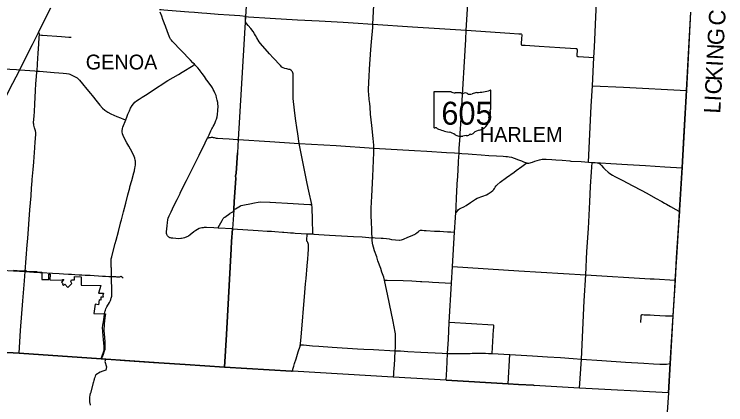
# Model space of a CAD drawing. Extents: x 1729596 to 1925846, y 659247 to 911751.
# Drawn here: x 1855559 to 1898765, y 773722 to 797404 of the extents above; entities that cross this region are included whole.
import ezdxf

# ---------------------------------------------------------------- set-up
doc = ezdxf.new("R2010")
doc.units = 0
for name, color, linetype in [('GM_X_Adjacent_County', 7, 'Continuous'), ('GM_X_Adjacent_County_Text', 7, 'Continuous'), ('GM_X_City_Street', 7, 'Continuous'), ('GM_X_Corporation', 7, 'Continuous'), ('GM_X_County', 7, 'Continuous'), ('GM_X_County_Road', 7, 'Continuous'), ('GM_X_State_Route', 7, 'Continuous'), ('GM_X_State_Shield', 7, 'Continuous'), ('GM_X_Township', 7, 'Continuous'), ('GM_X_Township_Road', 7, 'Continuous'), ('GM_X_Township_Text', 7, 'Continuous')]:
    doc.layers.add(name, color=color, linetype=linetype)

msp = doc.modelspace()

# ---------------------------------------------------------------- linework, layer by layer
at = {"layer": 'GM_X_Adjacent_County'}
msp.add_line((1895282, 774451), (1894201, 757542), dxfattribs=at)
at = {"layer": 'GM_X_City_Street'}
for points in [[(1852214, 782040), (1852297, 782035), (1852381, 782031), (1852490, 782023), (1853564, 781958), (1854813, 781882), (1856233, 781796), (1856759, 781767), (1857122, 781742)], [(1855849, 776844), (1855938, 778232), (1856080, 780022), (1856177, 781246), (1856233, 781796)], [(1860837, 776510), (1860876, 776625), (1861011, 777030), (1861019, 777105), (1861019, 777267), (1861005, 777431), (1860979, 777707), (1860959, 777869), (1860929, 778184), (1860926, 778385), (1860938, 778550), (1860970, 778758), (1861038, 779200), (1861042, 779227)], [(1851242, 777113), (1853977, 776957), (1854746, 776908), (1855849, 776844), (1860837, 776510)], [(1860837, 776510), (1861150, 776489)]]:
    msp.add_lwpolyline(points, dxfattribs=at)
at = {"layer": 'GM_X_Corporation'}
msp.add_lwpolyline([(1855515, 781881), (1855693, 781873), (1855739, 781870), (1855967, 781851), (1856168, 781841), (1856195, 781864), (1856211, 781863), (1856236, 781862), (1856261, 781860), (1856276, 781859), (1856299, 781833), (1856937, 781794), (1856936, 781779), (1857238, 781762), (1857236, 781737), (1857239, 781327), (1857650, 781308), (1857667, 781631), (1857667, 781633), (1857666, 781635), (1857665, 781638), (1857665, 781639), (1857663, 781642), (1857661, 781645), (1857661, 781645), (1857660, 781645), (1857658, 781647), (1857657, 781648), (1857656, 781648), (1857654, 781649), (1857652, 781650), (1857650, 781650), (1857750, 781644), (1857748, 781644), (1857746, 781643), (1857744, 781643), (1857743, 781642), (1857742, 781642), (1857739, 781640), (1857739, 781640), (1857739, 781639), (1857736, 781637), (1857734, 781634), (1857734, 781633), (1857732, 781631), (1857732, 781629), (1857731, 781626), (1857715, 781305), (1858491, 781268), (1858493, 781318), (1858578, 781314), (1858423, 781151), (1858532, 781048), (1858498, 781011), (1858552, 780960), (1858623, 781028), (1858823, 780839), (1859051, 781080), (1858990, 781189), (1859040, 781304), (1859215, 781299), (1859220, 781493), (1859628, 781482), (1859614, 780982), (1860814, 780950), (1860682, 780484), (1860982, 780480), (1860944, 780361), (1860968, 780237), (1860818, 780240), (1860815, 780064), (1860716, 780079), (1860671, 779783), (1860473, 779812), (1860389, 779255), (1861099, 779232), (1861059, 778991), (1861017, 778619), (1861001, 778196), (1861035, 777824), (1861063, 777515), (1861063, 777076), (1861027, 776964), (1860963, 776772), (1860875, 776576), (1860907, 776515), (1861104, 776501), (1861102, 776461), (1861067, 776346), (1861166, 776024), (1861129, 775818), (1860932, 775766), (1860782, 775695), (1860506, 775536), (1860490, 775500), (1860473, 775450), (1860446, 775373), (1860418, 775284), (1860408, 775252), (1860389, 775184), (1860366, 775102), (1860350, 775045), (1860186, 774433), (1860177, 774398), (1860167, 774360), (1860158, 774319), (1860150, 774274), (1860139, 774199), (1860132, 774101), (1860131, 774023), (1860133, 773962), (1860139, 773897), (1860151, 773806), (1860162, 773755), (1860176, 773694)], dxfattribs=at)
at = {"layer": 'GM_X_County'}
msp.add_lwpolyline([(1896629, 797539), (1896376, 792790), (1896278, 791042), (1896113, 788102), (1895956, 785523), (1895947, 785445), (1895896, 784633), (1895772, 782650), (1895741, 782103), (1895686, 781278), (1895557, 779101), (1895391, 776219), (1895282, 774451), (1889887, 774731), (1887135, 774898), (1887084, 774902), (1886187, 774949), (1885545, 774992), (1881788, 775208), (1878568, 775400), (1872453, 775754), (1872401, 775756), (1868321, 776001), (1865938, 776163), (1864331, 776270), (1860837, 776510), (1855849, 776844), (1854746, 776908)], dxfattribs=at)
at = {"layer": 'GM_X_County_Road'}
for points in [[(1877332, 796811), (1877420, 798367), (1877499, 799608), (1877454, 800633), (1877398, 802125), (1877369, 802994)], [(1857028, 796294), (1857277, 796797), (1857775, 797801)], [(1869596, 797271), (1869264, 797299), (1868606, 797350), (1867949, 797398), (1867262, 797449), (1866957, 797476), (1866512, 797510), (1866160, 797537), (1865389, 797594), (1864651, 797652), (1864490, 797665), (1864412, 797670), (1864397, 797669), (1864380, 797664)], [(1864668, 796879), (1864590, 797083), (1864513, 797287), (1864422, 797530)], [(1872512, 792112), (1872490, 792299), (1872490, 792441), (1872490, 792557), (1872490, 792879), (1872488, 793281), (1872492, 793732), (1872489, 793791), (1872473, 793859), (1872454, 793904), (1872424, 793943), (1872389, 793984), (1872352, 794016), (1872303, 794045), (1872239, 794060), (1872103, 794090), (1871997, 794120), (1871888, 794161), (1871806, 794204), (1871722, 794290), (1871282, 794757), (1871051, 795010), (1870503, 795638), (1870435, 795737), (1870300, 795980), (1870212, 796114), (1870156, 796211), (1870067, 796366), (1869918, 796549), (1869770, 796721), (1869677, 796824), (1869643, 796870), (1869617, 796918), (1869609, 796940), (1869604, 796966), (1869603, 796991), (1869604, 797040), (1869606, 797200), (1869596, 797271)], [(1869596, 797271), (1869794, 797255), (1871103, 797168), (1872753, 797073), (1874071, 797014), (1875527, 796924), (1876143, 796885), (1877332, 796811)], [(1896288, 791046), (1896384, 792784), (1896550, 795738), (1896641, 797536)], [(1866503, 794368), (1866405, 794466), (1866272, 794620), (1866088, 794799), (1865870, 795027), (1865711, 795195), (1865579, 795328), (1865290, 795631), (1865178, 795747), (1865101, 795824), (1865042, 795902), (1865004, 795980), (1864969, 796070), (1864868, 796347), (1864745, 796675), (1864687, 796830), (1864668, 796879)], [(1877401, 789284), (1877390, 789464), (1877348, 789877), (1877267, 790662), (1877198, 791335), (1877163, 791768), (1877144, 791994), (1877118, 792235), (1877082, 792567), (1877064, 792727), (1877062, 792815), (1877091, 793291), (1877116, 793631), (1877141, 794076), (1877219, 795256), (1877251, 795728), (1877331, 796597), (1877332, 796811)], [(1877332, 796811), (1879735, 796644), (1881379, 796538), (1883003, 796429), (1885646, 796260), (1886199, 796226), (1886342, 796212), (1886365, 796195), (1886376, 796165), (1886375, 796124), (1886362, 795947), (1886335, 795601), (1886339, 795571), (1886347, 795554), (1886359, 795544), (1886386, 795534), (1886593, 795523), (1887442, 795472), (1888679, 795387), (1889657, 795329), (1889685, 795326), (1889702, 795320), (1889718, 795310), (1889731, 795291), (1889734, 795271), (1889715, 794891), (1889718, 794875), (1889726, 794861), (1889758, 794850), (1889831, 794843), (1890758, 794790)], [(1851209, 784694), (1851326, 784936), (1852148, 786590), (1852443, 787187), (1853141, 788601), (1853675, 789667), (1853798, 789914), (1853979, 790280), (1854272, 790859), (1854392, 791103), (1854649, 791581), (1855260, 792799), (1855898, 794041), (1856273, 794777), (1856673, 795566), (1856869, 795971), (1857028, 796294)], [(1856946, 793960), (1856946, 793960), (1856971, 794394), (1857013, 795045), (1857051, 795598), (1857080, 796004), (1857092, 796153), (1857094, 796187), (1857090, 796216), (1857080, 796243), (1857067, 796263), (1857051, 796280), (1857028, 796294)], [(1862331, 790993), (1862331, 790993), (1862425, 791233), (1862464, 791347), (1862553, 791556), (1862621, 791712), (1862718, 791870), (1862878, 792073), (1862988, 792163), (1863137, 792257), (1863326, 792369), (1863622, 792566), (1863901, 792746), (1864887, 793380), (1865528, 793748), (1865763, 793892), (1866421, 794305), (1866453, 794326), (1866503, 794368)], [(1867241, 793436), (1867175, 793524), (1867110, 793619), (1866968, 793805), (1866845, 793974), (1866805, 794027), (1866710, 794146), (1866624, 794245), (1866569, 794300), (1866503, 794368)], [(1856233, 781796), (1856351, 783427), (1856379, 783803), (1856513, 785538), (1856582, 786399), (1856616, 786866), (1856649, 787292), (1856657, 787391), (1856707, 787988), (1856742, 788435), (1856768, 788759), (1856787, 788996), (1856839, 789647), (1856877, 790103), (1856879, 790157), (1856870, 790238), (1856843, 790340), (1856828, 790389), (1856789, 790519), (1856749, 790673), (1856741, 790738), (1856737, 790808), (1856738, 790844), (1856763, 791215), (1856781, 791498), (1856809, 791946), (1856855, 792786), (1856879, 793181), (1856895, 793405), (1856933, 793880), (1856936, 793913), (1856946, 793960)], [(1867153, 789604), (1867200, 789700), (1867319, 789935), (1867396, 790101), (1867504, 790327), (1867565, 790450), (1867596, 790512), (1867641, 790592), (1867690, 790690), (1867763, 790847), (1867804, 790955), (1867838, 791037), (1867877, 791180), (1867910, 791333), (1867929, 791569), (1867933, 791826), (1867927, 791967), (1867917, 792047), (1867886, 792196), (1867849, 792363), (1867813, 792478), (1867788, 792552), (1867745, 792648), (1867704, 792736), (1867647, 792848), (1867599, 792941), (1867524, 793055), (1867442, 793157), (1867330, 793312), (1867263, 793407), (1867241, 793436)], [(1872927, 777320), (1872945, 777432), (1872978, 777819), (1873212, 780520), (1873251, 781046), (1873282, 781384), (1873344, 782141), (1873381, 782566), (1873402, 782850), (1873426, 783163), (1873427, 783321), (1873418, 783441), (1873405, 783505), (1873393, 783554), (1873368, 783600), (1873335, 783652), (1873325, 783665), (1873319, 783693), (1873320, 783725), (1873324, 783797), (1873340, 783963), (1873351, 784093), (1873606, 784082), (1873683, 784083), (1873682, 784168), (1873669, 784889), (1873663, 785162), (1873657, 785466), (1873655, 785664), (1873627, 785869), (1873446, 786682), (1873351, 787142), (1872964, 789059), (1872863, 789571), (1872778, 790159), (1872727, 790526), (1872666, 790930), (1872604, 791411), (1872559, 791766), (1872513, 792107), (1872512, 792112)], [(1862860, 787938), (1862891, 788070), (1862911, 788154), (1862924, 788278), (1862924, 788410), (1862919, 788484), (1862909, 788555), (1862881, 788678), (1862846, 788780), (1862782, 788915), (1862621, 789214), (1862525, 789400), (1862401, 789615), (1862280, 789828), (1862168, 790041), (1862129, 790158), (1862118, 790274), (1862114, 790336), (1862129, 790467), (1862155, 790566), (1862331, 790993)], [(1895958, 785443), (1895961, 785520), (1896121, 788099), (1896226, 789994), (1896288, 791046)], [(1865634, 786531), (1865642, 786548), (1865861, 787020), (1866012, 787331), (1866508, 788298), (1866790, 788861), (1866977, 789237), (1867126, 789549), (1867153, 789604)], [(1872863, 789571), (1875101, 789435), (1877401, 789284), (1879855, 789132), (1880616, 789098), (1881806, 789028), (1882295, 788997), (1882567, 788975)], [(1878568, 775400), (1878590, 775455), (1878599, 775524), (1878604, 775641), (1878633, 775979), (1878640, 776088), (1878691, 776999), (1878702, 777191), (1878720, 777542), (1878720, 777749), (1878716, 777928), (1878712, 778020), (1878692, 778117), (1878562, 778774), (1878349, 779845), (1878222, 780426), (1878129, 780890), (1878049, 781278), (1877993, 781449), (1877886, 781763), (1877812, 781976), (1877647, 782454), (1877568, 782686), (1877444, 783047), (1877370, 783269), (1877325, 783417), (1877310, 783511), (1877305, 783560), (1877299, 783658), (1877295, 783854), (1877283, 784157), (1877278, 784375), (1877260, 784771), (1877240, 785195), (1877237, 785645), (1877265, 786378), (1877326, 787557), (1877396, 789022), (1877401, 789284)], [(1882567, 788975), (1882741, 788963), (1883125, 788937), (1883370, 788921), (1883909, 788888), (1884378, 788846), (1884839, 788818), (1885253, 788795), (1885410, 788787), (1885513, 788777), (1885610, 788763), (1885755, 788729), (1885907, 788682), (1886172, 788583), (1886362, 788508), (1886482, 788459), (1886595, 788414), (1886653, 788392), (1886680, 788385), (1886713, 788376), (1886731, 788374), (1886750, 788372), (1886768, 788373), (1886797, 788377), (1887028, 788442), (1887172, 788488), (1887461, 788573), (1887615, 788617), (1887686, 788622), (1887858, 788617), (1888201, 788587), (1888444, 788572), (1888821, 788548), (1889303, 788508), (1889365, 788503), (1889989, 788465), (1890439, 788430), (1890646, 788418), (1890829, 788409), (1890966, 788400), (1891025, 788386), (1891044, 788379), (1891062, 788369), (1891080, 788359), (1891096, 788347), (1891113, 788333), (1891216, 788229), (1891350, 788086), (1891449, 787991), (1891616, 787833), (1891727, 787741), (1891886, 787645), (1892027, 787567), (1892268, 787440), (1892505, 787318), (1892785, 787171), (1893118, 786998), (1893620, 786737), (1893978, 786545), (1894504, 786258), (1894890, 786043), (1895054, 785951), (1895157, 785895), (1895411, 785750), (1895736, 785562), (1895925, 785459), (1895958, 785443)], [(1861455, 782568), (1861484, 782698), (1861529, 782870), (1861693, 783500), (1861750, 783702), (1861886, 784220), (1862013, 784736), (1862018, 784757), (1862066, 784939), (1862201, 785417), (1862338, 785941), (1862465, 786443), (1862569, 786870), (1862577, 786904), (1862585, 786934), (1862693, 787317), (1862818, 787780), (1862854, 787912), (1862860, 787938)], [(1868321, 776001), (1868439, 777975), (1868734, 783178), (1868751, 783613), (1868806, 784389), (1867942, 784436), (1867676, 784450), (1867236, 784472), (1867100, 784466), (1867030, 784459), (1866941, 784445), (1866864, 784426), (1866789, 784401), (1866682, 784352), (1866580, 784287), (1866468, 784200), (1866242, 784020), (1866138, 783951), (1866042, 783902), (1865893, 783841), (1865807, 783819), (1865720, 783803), (1865668, 783796), (1865550, 783792), (1865186, 783818), (1865114, 783826), (1865049, 783836), (1865006, 783850), (1864986, 783859), (1864948, 783880), (1864897, 783921), (1864860, 783965), (1864838, 784001), (1864822, 784040), (1864798, 784100), (1864795, 784137), (1864796, 784206), (1864829, 784383), (1864841, 784568), (1864856, 784770), (1864885, 784933), (1864914, 785038), (1864961, 785176), (1865080, 785426), (1865258, 785787), (1865446, 786179), (1865634, 786531)], [(1895289, 774451), (1895396, 776220), (1895437, 776878), (1895549, 778840), (1895565, 779105), (1895662, 780753), (1895692, 781225), (1895695, 781277), (1895727, 781798), (1895781, 782638), (1895891, 784421), (1895958, 785443)], [(1868806, 784389), (1870363, 784286), (1870916, 784253), (1871172, 784239), (1871392, 784221), (1871840, 784193), (1871932, 784185), (1872143, 784168), (1872331, 784155), (1872524, 784144), (1872620, 784137), (1873351, 784093)], [(1861457, 781995), (1861454, 782060), (1861446, 782148), (1861441, 782263), (1861435, 782424), (1861446, 782529), (1861455, 782568)], [(1861464, 781502), (1861463, 781671), (1861461, 781880), (1861457, 781995)], [(1861042, 779227), (1861043, 779234), (1861066, 779359), (1861076, 779401), (1861095, 779466), (1861124, 779543), (1861142, 779583), (1861161, 779622), (1861188, 779670), (1861340, 779929), (1861381, 780006), (1861399, 780046), (1861420, 780097), (1861434, 780136), (1861446, 780176), (1861466, 780256), (1861476, 780305), (1861482, 780347), (1861487, 780389), (1861492, 780474), (1861490, 780645), (1861469, 781407), (1861464, 781502)], [(1872401, 775756), (1872432, 775766), (1872438, 775770), (1872452, 775785), (1872457, 775793), (1872468, 775823), (1872484, 775872), (1872540, 776071), (1872587, 776224), (1872678, 776514), (1872803, 776927), (1872912, 777278), (1872927, 777320)], [(1872927, 777320), (1872944, 777337), (1872954, 777344), (1872965, 777349), (1872976, 777353), (1872988, 777355), (1873000, 777356), (1873120, 777346), (1873673, 777303), (1874061, 777272), (1874867, 777216), (1876402, 777119), (1876790, 777089), (1877384, 777075), (1878691, 776999)], [(1878691, 776999), (1879006, 776989), (1879466, 776957), (1880249, 776920), (1881551, 776850), (1881869, 776825), (1882663, 776820), (1882987, 776825), (1883250, 776836), (1883358, 776844), (1883547, 776847), (1883777, 776854), (1884182, 776846), (1884360, 776836), (1884578, 776836), (1885651, 776777), (1887029, 776688), (1887936, 776629), (1888738, 776581), (1889498, 776517), (1890002, 776489), (1891247, 776403), (1892686, 776307), (1893785, 776247), (1894370, 776208), (1894763, 776177), (1895111, 776185), (1895167, 776190), (1895396, 776220)], [(1861150, 776489), (1861724, 776449)], [(1861724, 776449), (1862245, 776413)], [(1862245, 776413), (1864018, 776291)], [(1864018, 776291), (1864331, 776270)], [(1864331, 776270), (1865938, 776163), (1868321, 776001)], [(1868321, 776001), (1872401, 775756)]]:
    msp.add_lwpolyline(points, dxfattribs=at)
at = {"layer": 'GM_X_State_Route'}
for points in [[(1882720, 791504), (1882978, 795867), (1883003, 796429), (1883088, 797714), (1883392, 802588), (1883500, 804351), (1883543, 804938), (1883588, 805754), (1883679, 807097), (1883681, 807137)], [(1882488, 787572), (1882536, 788409), (1882544, 788490), (1882567, 788975), (1882584, 789282), (1882631, 789981), (1882641, 790234), (1882655, 790407), (1882720, 791504)], [(1881788, 775208), (1881798, 775531), (1881825, 775865), (1881869, 776825), (1881921, 777694), (1881972, 778710), (1882105, 781091), (1882171, 782101), (1882295, 784185), (1882344, 785085), (1882365, 785373), (1882388, 785663), (1882412, 786305), (1882436, 786610), (1882462, 787116), (1882488, 787572)]]:
    msp.add_lwpolyline(points, dxfattribs=at)
at = {"layer": 'GM_X_State_Shield'}
for p, q in [((1881028, 792671), (1881028, 790558)), ((1881028, 792671), (1881028, 790558)), ((1882082, 792708), (1881063, 792708)), ((1882082, 792708), (1881063, 792708)), ((1884509, 791655), (1884509, 792760)), ((1884509, 791655), (1884509, 792760)), ((1884508, 791655), (1884509, 791655)), ((1884508, 791655), (1884509, 791655))]:
    msp.add_line(p, q, dxfattribs=at)
for centre, major_axis, start_param, end_param in [((1881068, 792676), (40.3, 0), 1.712693, 3.28349), ((1881068, 792676), (40.3, 0), 1.712693, 3.28349), ((1882325, 792953), (391, 0), 4.042523, 4.731795), ((1882325, 792953), (391, 0), 4.042523, 4.731795), ((1882454, 791521), (1404, 0), 1.404758, 1.657858), ((1882454, 791521), (1404, 0), 1.404758, 1.657858), ((1882773, 792687), (113, 0), 3.836095, 5.185415), ((1882773, 792687), (113, 0), 3.836095, 5.185415), ((1882939, 792443), (235, 0), 0.950623, 2.079405), ((1882939, 792443), (235, 0), 0.950623, 2.079405), ((1883241, 792778), (282, 0), 4.081561, 5.145723), ((1883241, 792778), (282, 0), 4.081561, 5.145723), ((1883740, 792062), (743, 0), 1.699011, 2.107814), ((1883740, 792062), (743, 0), 1.699011, 2.107814), ((1883269, 795589), (3691, 0), 4.814394, 5.042369), ((1883269, 795589), (3691, 0), 4.814394, 5.042369), ((1884470, 792765), (38.7, 0), 6.141152, 7.989035), ((1884470, 792765), (38.7, 0), 6.141152, 7.989035), ((1884500, 791574), (60, 0), 1.883978, 3.671073), ((1884500, 791574), (60, 0), 1.883978, 3.671073), ((1884118, 791434), (360, 0), 5.934695, 6.695948), ((1884118, 791434), (360, 0), 5.934695, 6.695948), ((1884468, 791650), (41.5, 0), 5.05454, 6.418171), ((1884468, 791650), (41.5, 0), 5.05454, 6.418171), ((1883476, 791051), (923, 0), 5.101752, 6.440018), ((1883476, 791051), (923, 0), 5.101752, 6.440018), ((1884648, 791192), (262, 0), 2.387724, 3.262537), ((1884648, 791192), (262, 0), 2.387724, 3.262537), ((1881069, 790554), (40.7, 0), 3.00124, 4.508301), ((1881069, 790554), (40.7, 0), 3.00124, 4.508301), ((1881075, 790770), (310, 0), 4.665946, 4.897461), ((1881075, 790770), (310, 0), 4.665946, 4.897461), ((1881138, 790436), (112, 0), 0.519207, 1.627899), ((1881138, 790436), (112, 0), 0.519207, 1.627899), ((1882552, 792335), (2665, 0), 4.195997, 4.488961), ((1882552, 792335), (2665, 0), 4.195997, 4.488961), ((1881757, 789609), (834, 0), 0.823519, 1.323587), ((1881757, 789609), (834, 0), 0.823519, 1.323587), ((1883865, 789965), (506, 0), 1.647645, 2.488434), ((1883865, 789965), (506, 0), 1.647645, 2.488434), ((1882659, 790426), (529, 0), 4.026481, 4.996735), ((1882659, 790426), (529, 0), 4.026481, 4.996735), ((1882965, 789695), (435, 0), 1.495662, 1.94098), ((1882965, 789695), (435, 0), 1.495662, 1.94098), ((1883003, 790268), (282, 0), 4.691044, 5.507374), ((1883003, 790268), (282, 0), 4.691044, 5.507374), ((1883258, 790063), (79.4, 0), 1.147584, 2.315152), ((1883258, 790063), (79.4, 0), 1.147584, 2.315152), ((1883224, 790353), (298, 0), 4.937069, 5.64225), ((1883224, 790353), (298, 0), 4.937069, 5.64225)]:
    msp.add_ellipse(centre, major_axis=major_axis, ratio=0.8, start_param=start_param, end_param=end_param, dxfattribs=at)
at = {"layer": 'GM_X_Township'}
msp.add_lwpolyline([(1855512, 804546), (1855904, 804520), (1856177, 804502), (1856300, 804491), (1856579, 804475), (1858107, 804378), (1864561, 803926), (1870008, 803514), (1869596, 797271), (1869163, 789806), (1869111, 789007), (1869039, 787768), (1869000, 787580), (1869008, 787459), (1868914, 786029), (1868892, 785569), (1868890, 785515), (1868806, 784389), (1868751, 783613), (1868734, 783178), (1868439, 777975), (1868321, 776001)], dxfattribs=at)
at = {"layer": 'GM_X_Township_Road'}
for points in [[(1890439, 788430), (1890599, 791825), (1890663, 793067), (1890758, 794790), (1890789, 795400), (1890905, 797697), (1891157, 802023), (1891165, 802089), (1891207, 802088)], [(1857092, 796153), (1857218, 796138), (1857278, 796132), (1858429, 796050), (1858876, 796019), (1859017, 796010)], [(1853911, 794167), (1854809, 794108), (1855052, 794090), (1855289, 794075), (1855696, 794051), (1855898, 794041), (1856800, 793974), (1856946, 793960)], [(1856946, 793960), (1857092, 793949), (1857542, 793914), (1857978, 793881), (1858274, 793854), (1858527, 793830), (1858733, 793811), (1858865, 793782), (1858933, 793763), (1859024, 793732), (1859146, 793672), (1859290, 793592), (1859376, 793539), (1859523, 793403), (1859714, 793187), (1859975, 792860), (1860182, 792601), (1860283, 792472), (1860603, 792087), (1860762, 791885), (1860922, 791702), (1861069, 791579), (1861235, 791461), (1861427, 791357), (1861779, 791208), (1862012, 791128), (1862197, 791047), (1862331, 790993)], [(1890663, 793067), (1892550, 792979), (1896384, 792784)], [(1867319, 789935), (1867341, 789922), (1867365, 789918), (1867384, 789918), (1867408, 789922), (1867479, 789935), (1867531, 789940), (1867600, 789940), (1867638, 789937), (1867706, 789923), (1867821, 789895), (1867896, 789887), (1868229, 789864), (1868613, 789842), (1869090, 789811)], [(1869090, 789811), (1869163, 789806), (1871085, 789686), (1872863, 789571)], [(1868892, 785569), (1868914, 786029), (1869008, 787459), (1869000, 787580), (1869039, 787768), (1869111, 789007)], [(1882683, 785641), (1882855, 785721), (1882997, 785815), (1883257, 785993), (1883565, 786185), (1883679, 786242), (1884012, 786364), (1884230, 786446), (1884346, 786511), (1884516, 786635), (1884621, 786715), (1884686, 786778), (1884731, 786841), (1884769, 786909), (1884825, 787001), (1884855, 787037), (1884882, 787064), (1885068, 787213), (1885458, 787501), (1885907, 787835), (1886041, 787935), (1886384, 788169), (1886469, 788228), (1886553, 788290), (1886680, 788385)], [(1889887, 774731), (1890002, 776489), (1890176, 780026), (1890259, 781603), (1890338, 783022), (1890423, 784415), (1890516, 786023), (1890561, 786967), (1890617, 787839), (1890646, 788418)], [(1890966, 788400), (1891033, 788396), (1891153, 788392), (1891791, 788356), (1892800, 788289), (1893883, 788232), (1895073, 788154), (1896121, 788099)], [(1869311, 785786), (1869335, 785796), (1869538, 785844), (1869873, 785912), (1870158, 785969), (1870363, 786009), (1870524, 786025), (1871080, 786004), (1871097, 786003)], [(1871097, 786003), (1872502, 785926), (1873145, 785890), (1873503, 785869), (1873627, 785869)], [(1867942, 784436), (1867949, 784478), (1868023, 784612), (1868101, 784749), (1868183, 784905), (1868256, 785017), (1868303, 785069), (1868353, 785099), (1868641, 785317), (1868679, 785339), (1868830, 785413), (1868860, 785439), (1868876, 785462), (1868890, 785515), (1868891, 785527)], [(1868891, 785527), (1868892, 785569), (1868902, 785570)], [(1868902, 785570), (1868932, 785574), (1869001, 785603), (1869292, 785779), (1869311, 785786)], [(1882365, 785373), (1882398, 785385), (1882433, 785419), (1882534, 785556), (1882606, 785605), (1882683, 785641)], [(1878710, 783724), (1878718, 783723), (1878952, 783700), (1878974, 783698), (1879074, 783716), (1879141, 783735), (1879196, 783761), (1879454, 783879), (1879626, 783945), (1879759, 784003), (1879901, 784076), (1879948, 784106), (1880010, 784152), (1880078, 784216), (1880118, 784255), (1880153, 784278), (1880179, 784290), (1880195, 784296), (1880230, 784302), (1880247, 784303), (1880334, 784300), (1880449, 784295), (1880574, 784290), (1881079, 784258), (1881400, 784242), (1881619, 784230), (1881872, 784212), (1882079, 784200), (1882295, 784185)], [(1873683, 784083), (1873753, 784073), (1874065, 784055), (1874709, 784010), (1876165, 783928), (1876686, 783898), (1877295, 783854)], [(1877295, 783854), (1877356, 783857), (1877485, 783848), (1877833, 783829), (1877952, 783822), (1878166, 783809), (1878334, 783779), (1878476, 783745), (1878710, 783724)], [(1882171, 782101), (1886206, 781843), (1890259, 781603)], [(1857122, 781742), (1857219, 781736), (1857889, 781699), (1858283, 781677), (1858541, 781662), (1858852, 781645), (1859041, 781634), (1859231, 781623), (1859493, 781610), (1859657, 781600), (1859871, 781588), (1860167, 781572), (1860916, 781528), (1861102, 781518)], [(1890259, 781603), (1890259, 781603), (1894179, 781364)], [(1861102, 781518), (1861300, 781508), (1861464, 781502)], [(1861464, 781502), (1861718, 781503), (1861769, 781478), (1861847, 781475), (1861935, 781477), (1861968, 781482), (1862010, 781496), (1862047, 781518), (1862117, 781450), (1862183, 781413)], [(1878049, 781278), (1878201, 781278), (1879179, 781250), (1879698, 781229), (1880226, 781199), (1880311, 781191), (1880734, 781168), (1880958, 781163), (1882105, 781091)], [(1894179, 781364), (1894411, 781350), (1895695, 781277)], [(1893617, 778714), (1893624, 779045), (1893632, 779127), (1893640, 779161), (1893657, 779180), (1893679, 779187), (1893716, 779191), (1893800, 779184), (1893892, 779175), (1894041, 779168), (1894167, 779168), (1894412, 779159), (1895102, 779119), (1895565, 779105)], [(1884666, 778287), (1884672, 778396), (1884683, 778518), (1884681, 778531), (1884671, 778543), (1884647, 778546), (1883334, 778630), (1881972, 778710)], [(1884578, 776836), (1884646, 777916), (1884666, 778287)], [(1885545, 774992), (1885651, 776777)], [(1881788, 775208), (1885545, 774992), (1886187, 774949), (1887084, 774902), (1887135, 774898)]]:
    msp.add_lwpolyline(points, dxfattribs=at)

# ---------------------------------------------------------------- texts
at = {"layer": 'GM_X_Adjacent_County_Text'}
for s, rotation, p in [('C', 86.4487, (1898710, 796690)), ('G', 86.9419, (1898647, 795506)), ('N', 86.9747, (1898600, 794623)), ('K', 86.9789, (1898532, 793332)), ('I', 86.9739, (1898579, 794215)), ('C', 86.98, (1898489, 792519)), ('I', 86.9808, (1898468, 792110)), ('L', 86.9798, (1898428, 791363))]:
    msp.add_text(s, height=1000, rotation=rotation, dxfattribs=at).set_placement(p)
at = {"layer": 'GM_X_State_Shield'}
msp.add_text('605', height=1392.2, dxfattribs=at).set_placement((1881497, 790707))
msp.add_text('605', height=1392.2, dxfattribs=at).set_placement((1881497, 790707))
at = {"layer": 'GM_X_Township_Text'}
for s, p in [('GENOA', (1859903, 794055)), ('HARLEM', (1883833, 789665))]:
    msp.add_text(s, height=900, rotation=0, dxfattribs=at).set_placement(p)

doc.saveas('drawing.dxf')
